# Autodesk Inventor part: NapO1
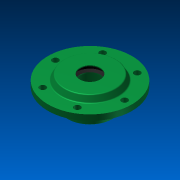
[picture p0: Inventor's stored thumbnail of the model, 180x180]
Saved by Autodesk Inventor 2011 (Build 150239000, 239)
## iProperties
Created: 2011-05
Part Number: NapO1
Document SubType Name: Modeling
Designer: 904Chiaki
Density: 1 g/cm^3
Mass: 222.808 g
Surface Area: 586.853 cm^2
Volume: 222.808 cm^3
Author: 904Chiaki
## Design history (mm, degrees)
sketch "Sketch1"
  geometry: C1 r 74 at (-17.134, 0); 1 further point
  constraints: 1 centre point
  dimensions: "d0" = 148 diameter of C1
extrude "Extrusion1" new body sketch "Sketch1" distance "d1" = 10; taper "d2" = 0 deg
sketch "Sketch2"
  geometry: C1 r 74 at (0, 0) reference; C2 r 50 at (0, 0); 1 further point
  constraints: 1 centre point, 1 coincident
  dimensions: "d3" = 100 diameter of C2
extrude "Extrusion2" join sketch "Sketch2" distance "d4" = 10; taper "d5" = 0 deg
sketch "Sketch3"
  geometry: C1 r 74 at (0, 0) reference; C2 r 35 at (0, 0); 1 further point
  constraints: 1 centre point, 1 coincident
  dimensions: "d6" = 70 diameter of C2
extrude "Extrusion3" cut sketch "Sketch3" distance "d7" = 8; taper "d8" = 0 deg
chamfer "Chamfer1" distance "d10" = 10; stored, may be unused: second distance "d11" = 5, angle "d12" = 45 deg
sketch "Sketch4"
  geometry: C1 r 35 at (0, 0) reference; C2 r 74 at (0, 0) reference; C3 r 39 at (0, 0); 1 further point
  constraints: 1 centre point, 1 coincident
  dimensions: "d13" = 78 diameter of C3
extrude "Extrusion4" join sketch "Sketch4" distance "d14" = 2; taper "d15" = 0 deg
sketch "Sketch5"
  geometry: C1 r 35 at (0, 0) reference; C2 r 39 at (0, 0) reference; C3 r 40 at (0, 0); 1 further point
  constraints: 1 centre point, 1 coincident
  dimensions: "d16" = 80 diameter of C3
extrude "Extrusion5" join sketch "Sketch5" distance "d17" = 28; taper "d18" = 0 deg
sketch "Sketch6"
  geometry: C1 r 35 at (0, 0) reference; C2 r 18 at (0, 0); 1 further point
  constraints: 1 centre point, 1 coincident
  dimensions: "d19" = 36 diameter of C2
extrude "Extrusion6" cut sketch "Sketch6" stored distance "d20" = 26; taper "d21" = 0 deg
workplane "Work Plane1"
  workaxis "Work Axis1"
fillet "Fillet1" dims "d23" = 2
fillet "Fillet2" dims "d24" = 2
chamfer "Chamfer2" distance "d25" = 1; stored, may be unused: second distance "d26" = 5, angle "d27" = 45 deg
sketch "Sketch7"
  geometry: L1 (6, 24)-(9.25, 24); L2 (10.5, 18)-(9.25, 24); L3 (1.5, 18)-(2.75, 24); L4 (6, 24)-(2.75, 24); L5 (10.5, 18)-(1.5, 18); L6 (-48, 0)-(22, 0) reference; 1 further point
  constraints: 10 end point
  dimensions: "d29" = 3.25 distance of L1.start L1.end
revolve "Revolution1" sketch "Sketch7" stored, may be unused: angle "d31" = 90 deg
workpoint "Work Point1"
workpoint "Work Point2"
workpoint "Work Point3"
workpoint "Work Point4"
workpoint "Work Point5"
workpoint "Work Point6"
node "Hole2"
body "Solid1"
sketch "Sketch9"
  geometry: 6 further points
hole "Hole1" sketch "Sketch9" diameter "d38" = 11; stored, may be unused: countersink angle "d42" = 90 deg, drill point angle "d44" = 0 deg; dims "d39" = 6, "d40" = 4, "d41" = 2, "d43" = 8
other parameters: "d22" = 90 deg
